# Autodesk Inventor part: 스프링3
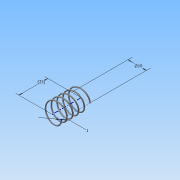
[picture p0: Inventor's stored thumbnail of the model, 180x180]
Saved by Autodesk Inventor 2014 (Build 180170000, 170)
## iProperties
Created: 2015-06
Part Number: 스프링3
Material: 강철, 연강
Document SubType Name: Modeling
Designer: Administrator
Density: 7.86 g/cm^3
Appearance: 강철
Mass: 1.53479 g
Surface Area: 7.89194 cm^2
Volume: 0.195266 cm^3
Author: Administrator
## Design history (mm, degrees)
sketch "스케치1"
  geometry: L1 (0, 0)-(8, 0); L2 (8, 0)-(8, 21.5); L3 (8, 21.5)-(0, 21.5); L4 (0, 21.5)-(0, 0); C1 r 0.5 at (8, 0)
  constraints: 8 end point, 2 parallel, 1 centre point, 1 coincident, 1 horizontal, 1 perpendicular
  dimensions: "d0" = 21.5 distance of L3.end L1.start (derived); "d1" = 16 diameter of L2 L4; "d2" = 1 diameter of C1
feature "코일1" sketch "스케치1" pitch "d3" = 10; turns "d5" = 5; dims "d4" = 21.5 (= d0), "d6" = 0, angle "d7" = 90 deg, angle "d8" = 90 deg, "d9" = 0, "d10" = 0
sketch "스케치2"
  geometry: L1 (-8.5, 0)-(-7.5, 0) reference; 1 further point
  constraints: 1 horizontal alignment
extrude "돌출1" cut sketch "스케치2" stored distance "d11" = 10; taper "d12" = 0 deg
node "작업 평면1"
sketch "스케치3"
  geometry: L1 (-7.5, 0)-(-8.5, 0) reference; 1 further point
  constraints: 1 horizontal alignment
extrude "돌출2" cut sketch "스케치3" stored distance "d14" = 10; taper "d15" = 0 deg
node "솔리드1"
node "절단 모서리 투영1"
node "절단 모서리 투영2"
other parameters: "d13" = 21.5 (= d0)
